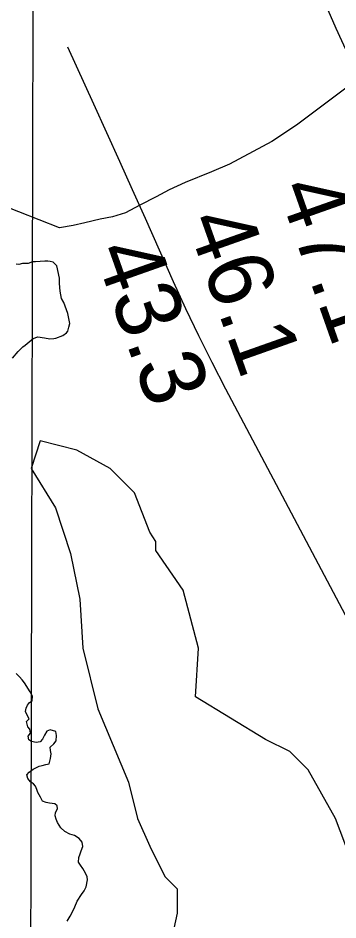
# Model space of a CAD drawing. Extents: x 3187622 to 3225504, y 800805 to 826213.
# Drawn here: x 3197048 to 3197378, y 818987 to 819917 of the extents above; entities that cross this region are included whole.
import ezdxf

# ---------------------------------------------------------------- set-up
doc = ezdxf.new("R2010")
doc.units = 0
for name, color, linetype in [('V-GRID-MAJR', 7, 'Continuous'), ('V-RIVR-RANG', 7, 'Continuous'), ('V-SITE-VEGE', 7, 'Continuous'), ('V-TOPO-MINR', 7, 'Continuous'), ('V-TOPO-SHOR', 7, 'Continuous')]:
    doc.layers.add(name, color=color, linetype=linetype)

msp = doc.modelspace()

# ---------------------------------------------------------------- linework, layer by layer
at = {"layer": 'V-GRID-MAJR'}
msp.add_spline([(3197031.47, 806236.813), (3197045.574, 812297.071), (3197059.682, 818359.272), (3197073.789, 824421.511), (3197073.793, 824423.414)], degree=3, dxfattribs=at)
at = {"layer": 'V-SITE-VEGE'}
for p, q in [((3197062.561, 819665.997), (3197058.276, 819664.344)), ((3197065.782, 819666.028), (3197062.561, 819665.997)), ((3197075.447, 819666.657), (3197065.782, 819666.028)), ((3197078.67, 819666.685), (3197075.447, 819666.657)), ((3197080.825, 819666.169), (3197078.67, 819666.685)), ((3197084.052, 819665.661), (3197080.825, 819666.169)), ((3197087.849, 819661.938), (3197084.052, 819665.661)), ((3197048.6180000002, 819663.179), (3197045.927, 819663.6910000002)), ((3197052.3680000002, 819664.289), (3197048.6180000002, 819663.179)), ((3197058.276, 819664.344), (3197052.3680000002, 819664.289)), ((3197090.657, 819649.0700000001), (3197087.849, 819661.938)), ((3197090.7060000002, 819643.698), (3197090.657, 819649.0700000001)), ((3197091.321, 819635.6460000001), (3197090.7060000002, 819643.698)), ((3197092.466, 819628.136), (3197091.321, 819635.6460000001)), ((3197095.194, 819623.8640000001), (3197092.466, 819628.136)), ((3197097.95, 819616.368), (3197095.194, 819623.8640000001)), ((3197099.06, 819612.618), (3197097.95, 819616.368)), ((3197101.305, 819602.429), (3197099.06, 819612.618)), ((3197100.2660000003, 819598.661), (3197101.305, 819602.429)), ((3197093.901, 819590.0040000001), (3197097.637, 819592.726)), ((3197097.637, 819592.726), (3197099.232, 819594.35)), ((3197099.232, 819594.35), (3197100.2660000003, 819598.661)), ((3197055.315, 819579.969), (3197063.306, 819587.028)), ((3197063.306, 819587.028), (3197068.125, 819588.687)), ((3197068.125, 819588.687), (3197075.119, 819587.677)), ((3197075.119, 819587.677), (3197080.503, 819586.653)), ((3197080.503, 819586.653), (3197084.8000000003, 819586.694)), ((3197084.8000000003, 819586.694), (3197086.944, 819587.251)), ((3197086.944, 819587.251), (3197093.901, 819590.0040000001)), ((3197042.011, 819566.411), (3197047.8540000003, 819573.452)), ((3197047.8540000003, 819573.452), (3197052.642, 819578.332)), ((3197052.642, 819578.332), (3197055.315, 819579.969)), ((3197070.609, 819481.202), (3197061.191, 819452.929)), ((3197108.284, 819471.777), (3197070.609, 819481.202)), ((3197142.818, 819452.929), (3197108.284, 819471.777)), ((3197061.191, 819452.929), (3197086.307, 819412.0920000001)), ((3197167.934, 819427.7980000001), (3197142.818, 819452.929)), ((3197183.632, 819386.963), (3197167.934, 819427.7980000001)), ((3197086.307, 819412.0920000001), (3197102.005, 819364.97)), ((3197189.912, 819377.5380000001), (3197183.632, 819386.963)), ((3197189.912, 819368.115), (3197189.912, 819377.5380000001)), ((3197218.166, 819327.2760000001), (3197189.912, 819368.115)), ((3197102.005, 819364.97), (3197111.424, 819317.851)), ((3197233.864, 819267.591), (3197218.166, 819327.2760000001)), ((3197111.424, 819317.851), (3197114.5640000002, 819267.591)), ((3197114.5640000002, 819267.591), (3197130.259, 819204.765)), ((3197230.724, 819217.331), (3197233.864, 819267.591)), ((3197049.241, 819237.7660000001), (3197045.915, 819241.248)), ((3197052.122, 819234.938), (3197049.241, 819237.7660000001)), ((3197054.565, 819231.887), (3197052.122, 819234.938)), ((3197060.367, 819222.281), (3197054.565, 819231.887)), ((3197062.6040000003, 819217.909), (3197060.367, 819222.281)), ((3197057.4220000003, 819208.638), (3197059.591, 819211.294)), ((3197059.591, 819211.294), (3197062.208, 819213.295)), ((3197062.208, 819213.295), (3197062.6040000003, 819217.909)), ((3197302.932, 819173.3509999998), (3197230.724, 819217.331)), ((3197055.505, 819202.252), (3197056.13, 819205.77)), ((3197056.853, 819198.969), (3197055.505, 819202.252)), ((3197056.13, 819205.77), (3197057.4220000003, 819208.638)), ((3197130.259, 819204.765), (3197161.6550000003, 819129.3719999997)), ((3197056.701, 819191.942), (3197059.311, 819194.601)), ((3197057.85, 819186.464), (3197056.701, 819191.942)), ((3197059.311, 819194.601), (3197056.853, 819198.969)), ((3197059.849, 819184.066), (3197057.85, 819186.464)), ((3197060.548, 819179.9), (3197059.849, 819184.066)), ((3197077.659, 819181.819), (3197075.062, 819177.623)), ((3197080.9390000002, 819183.167), (3197077.659, 819181.819)), ((3197086.8850000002, 819181.4670000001), (3197080.9390000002, 819183.167)), ((3197058.383, 819176.586), (3197060.548, 819179.9)), ((3197058.856, 819173.074), (3197058.383, 819176.586)), ((3197061.725, 819171.348), (3197058.856, 819173.0740000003)), ((3197073.124, 819173.652), (3197070.515, 819170.77)), ((3197075.062, 819177.623), (3197073.124, 819173.652)), ((3197087.362, 819177.518), (3197086.8850000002, 819181.4670000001)), ((3197086.975, 819171.804), (3197087.362, 819177.518)), ((3197328.049, 819160.7859999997), (3197302.932, 819173.3509999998)), ((3197066.35, 819170.074), (3197061.725, 819171.3479999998)), ((3197070.515, 819170.77), (3197066.35, 819170.074)), ((3197081.107, 819165.384), (3197084.589, 819168.71)), ((3197081.1380000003, 819162.089), (3197081.107, 819165.384)), ((3197084.589, 819168.71), (3197086.975, 819171.804)), ((3197081.83, 819158.5800000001), (3197081.1380000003, 819162.089)), ((3197081.4390000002, 819153.5260000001), (3197081.83, 819158.5800000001)), ((3197346.8850000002, 819141.9379999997), (3197328.049, 819160.7859999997)), ((3197063.3140000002, 819142.8150000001), (3197069.6550000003, 819145.729)), ((3197069.6550000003, 819145.729), (3197072.723, 819146.415)), ((3197072.723, 819146.415), (3197076.448, 819147.331)), ((3197076.448, 819147.331), (3197079.952, 819148.242)), ((3197079.952, 819148.2419999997), (3197081.4390000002, 819153.5260000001)), ((3197057.005, 819136.827), (3197059.392, 819139.485)), ((3197057.916, 819133.101), (3197057.005, 819136.827)), ((3197059.392, 819139.485), (3197063.3140000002, 819142.8150000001)), ((3197375.1410000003, 819091.676), (3197346.8850000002, 819141.9379999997)), ((3197060.5840000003, 819129.6140000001), (3197057.916, 819133.101)), ((3197063.898, 819127.449), (3197060.5840000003, 819129.6140000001)), ((3197065.897, 819125.0530000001), (3197063.898, 819127.449)), ((3197161.6550000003, 819129.3719999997), (3197171.074, 819091.674)), ((3197067.025, 819121.77), (3197065.897, 819125.0530000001)), ((3197068.373, 819118.708), (3197067.025, 819121.77)), ((3197070.835, 819113.899), (3197068.373, 819118.708)), ((3197073.069, 819109.748), (3197070.835, 819113.899)), ((3197076.8170000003, 819108.245), (3197073.069, 819109.7479999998)), ((3197080.335, 819107.618), (3197076.8170000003, 819108.2450000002)), ((3197085.613, 819107.012), (3197080.335, 819107.618)), ((3197088.267, 819104.841), (3197085.613, 819107.012)), ((3197086.576, 819098.019), (3197088.515, 819101.769)), ((3197088.515, 819101.769), (3197088.267, 819104.841)), ((3197086.166, 819094.7199999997), (3197086.576, 819098.019)), ((3197087.0810000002, 819090.996), (3197086.166, 819094.7199999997)), ((3197088.429, 819087.716), (3197087.0810000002, 819090.996)), ((3197171.074, 819091.674), (3197183.63, 819063.404)), ((3197390.839, 819050.839), (3197375.1410000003, 819091.676)), ((3197091.995, 819082.258), (3197088.429, 819087.716)), ((3197096.201, 819078.5650000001), (3197091.995, 819082.258)), ((3197101.059, 819075.755), (3197096.201, 819078.5650000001)), ((3197105.9050000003, 819074.264), (3197101.059, 819075.755)), ((3197110.767, 819071.0160000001), (3197105.9050000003, 819074.264)), ((3197113.875, 819067.313), (3197110.767, 819071.0160000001)), ((3197113.0810000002, 819058.5210000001), (3197114.576, 819062.929)), ((3197114.576, 819062.929), (3197113.875, 819067.313)), ((3197183.63, 819063.404), (3197199.328, 819031.9890000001)), ((3197110.5130000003, 819051.47), (3197112.012, 819055.437)), ((3197112.012, 819055.437), (3197113.0810000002, 819058.5210000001)), ((3197110.117, 819046.639), (3197110.5130000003, 819051.47)), ((3197112.122, 819043.581), (3197110.117, 819046.639)), ((3197114.5700000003, 819040.311), (3197112.122, 819043.581)), ((3197117.47, 819035.506), (3197114.5700000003, 819040.311)), ((3197119.262, 819031.7909999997), (3197117.47, 819035.506)), ((3197118.041, 819021.459), (3197119.512, 819028.498)), ((3197119.512, 819028.498), (3197119.262, 819031.7909999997)), ((3197199.328, 819031.9890000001), (3197211.887, 819019.425)), ((3197113.288, 819013.287), (3197115.887, 819017.262)), ((3197115.887, 819017.262), (3197118.041, 819021.459)), ((3197211.887, 819019.425), (3197211.887, 818994.294)), ((3197106.38, 819000.704), (3197108.96, 819006.441)), ((3197108.96, 819006.441), (3197113.288, 819013.287)), ((3197101.639, 818991.218), (3197104.225, 818996.2930000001)), ((3197104.225, 818996.2930000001), (3197106.38, 819000.704)), ((3197098.393, 818985.9180000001), (3197101.639, 818991.218)), ((3197211.887, 818994.294), (3197202.47, 818950.3150000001))]:
    msp.add_line(p, q, dxfattribs=at)
at = {"layer": 'V-TOPO-MINR'}
for points in [[(3197327.953917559, 820016.5034057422), (3197375.7331817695, 819906.8122674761), (3197474.3693122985, 819692.2435476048)], [(3197614.748015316, 818955.7877410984), (3197561.1520158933, 819017.5218615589), (3197530.1360317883, 819055.8256322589), (3197500.970934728, 819095.3980835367), (3197474.5821682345, 819136.873555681), (3197450.0442887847, 819179.6177084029), (3197262.070225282, 819534.7397916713), (3197247.948232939, 819562.0814144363), (3197234.1974728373, 819589.6038656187), (3197221.003561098, 819617.3975594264), (3197208.1808816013, 819645.3720816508), (3197179.1146752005, 819710.5075508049), (3197165.902069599, 819740.0263922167), (3197152.645009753, 819769.5251949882), (3197139.3212685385, 819798.9939398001), (3197125.953073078, 819828.442645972), (3197099.15, 819887.31)]]:
    msp.add_lwpolyline(points, dxfattribs=at)
at = {"layer": 'V-TOPO-SHOR'}
for points in [[(3197392.688, 819850.049), (3197335.0270000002, 819806.9400000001), (3197309.453, 819789.872), (3197299.932, 819784.832), (3197265.792, 819766.693), (3197247.3910000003, 819758.601), (3197220.109, 819747.786), (3197203.684, 819740.042), (3197190.225, 819732.985), (3197173.48, 819724.248), (3197158.7060000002, 819716.5210000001), (3197145.218, 819712.433), (3197132.373, 819710.002), (3197116.571, 819706.226), (3197104.719, 819703.473), (3197090.555, 819701.03), (3197069.694, 819709.081), (3197048.497, 819717.459), (3197028.957, 819725.192)], [(3197101.059, 819075.755), (3197096.201, 819078.5650000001), (3197091.995, 819082.258), (3197088.429, 819087.716), (3197087.0810000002, 819090.996), (3197086.168, 819094.72), (3197086.576, 819098.017), (3197088.515, 819101.769), (3197088.267, 819104.841), (3197085.613, 819107.012), (3197080.335, 819107.62), (3197076.8170000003, 819108.247), (3197073.069, 819109.748), (3197070.835, 819113.899), (3197068.373, 819118.708), (3197067.025, 819121.77), (3197065.897, 819125.0530000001), (3197063.898, 819127.449), (3197060.5840000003, 819129.6140000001), (3197057.916, 819133.101), (3197057.002, 819136.827), (3197059.392, 819139.485), (3197063.3140000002, 819142.8150000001), (3197069.6550000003, 819145.729), (3197072.723, 819146.417), (3197076.446, 819147.331), (3197079.952, 819148.242), (3197081.4390000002, 819153.5260000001), (3197081.83, 819158.5800000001), (3197081.1380000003, 819162.089), (3197081.107, 819165.382), (3197084.589, 819168.71), (3197086.975, 819171.804), (3197087.362, 819177.518), (3197086.8850000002, 819181.4670000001), (3197080.9390000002, 819183.167), (3197077.659, 819181.819), (3197075.062, 819177.623), (3197073.124, 819173.652), (3197070.515, 819170.77), (3197066.35, 819170.074), (3197061.725, 819171.348), (3197058.856, 819173.076), (3197058.383, 819176.586), (3197060.548, 819179.9), (3197059.849, 819184.066), (3197057.85, 819186.464), (3197056.701, 819191.942), (3197059.311, 819194.601), (3197056.855, 819198.969), (3197055.505, 819202.252), (3197056.13, 819205.77), (3197057.42, 819208.638), (3197059.591, 819211.294), (3197062.208, 819213.295), (3197062.6040000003, 819217.909), (3197060.367, 819222.279), (3197054.565, 819231.887), (3197052.122, 819234.938), (3197049.241, 819237.7660000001), (3197045.915, 819241.248)], [(3197098.395, 818985.9180000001), (3197101.639, 818991.218), (3197104.225, 818996.2930000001), (3197106.38, 819000.704), (3197108.96, 819006.439), (3197113.288, 819013.287), (3197115.887, 819017.264), (3197118.041, 819021.459), (3197119.512, 819028.498), (3197119.262, 819031.791), (3197117.47, 819035.506), (3197114.5700000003, 819040.311), (3197112.122, 819043.581), (3197110.117, 819046.637), (3197110.5130000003, 819051.47), (3197112.012, 819055.437), (3197113.0810000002, 819058.5210000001), (3197114.576, 819062.929), (3197113.875, 819067.313), (3197110.767, 819071.0160000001), (3197105.9050000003, 819074.264), (3197101.059, 819075.755)]]:
    msp.add_lwpolyline(points, dxfattribs=at)

# ---------------------------------------------------------------- texts
at = {"layer": 'V-RIVR-RANG'}
for s, p in [('47.1', (3197315.0850914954, 819741.8895395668)), ('46.1', (3197220.8890914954, 819708.3165395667)), ('43.3', (3197125.901475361, 819676.9816849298))]:
    msp.add_text(s, height=67.00000000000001, rotation=289.47832571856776, dxfattribs=at).set_placement(p)

doc.saveas('drawing.dxf')
